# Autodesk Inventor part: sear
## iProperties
Created: 2006-04
Part Number: sear
Document SubType Name: Modeling
Designer: Калинин
Author: Калинин
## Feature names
1. Выдавливание1 [Extrusion]
2. Выдавливание2 [Extrusion]
3. Выдавливание3 [Extrusion]
4. Выдавливание4 [Extrusion]
5. Сопряжение1 [Fillet]
